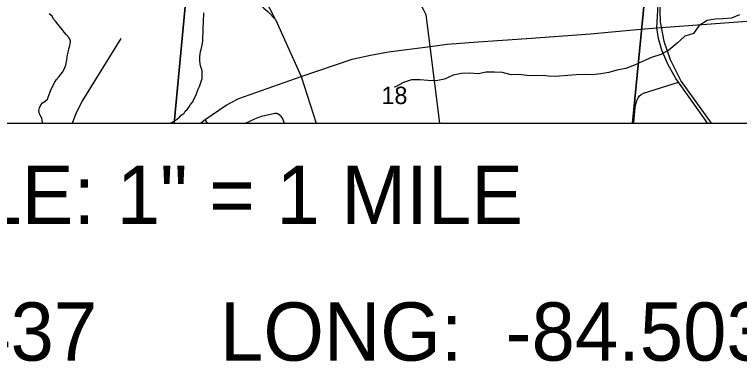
# Model space of a CAD drawing. Extents: x 0 to 34, y 0 to 22.
# Drawn here: x 12.335 to 14.078, y 12.863 to 13.697 of the extents above; entities that cross this region are included whole.
import ezdxf

# ---------------------------------------------------------------- set-up
doc = ezdxf.new("R2010")
doc.units = 0
for name, color, linetype in [('GM_X_City_Street', 7, 'Continuous'), ('GM_X_County_Road', 7, 'Continuous'), ('GM_X_Minor_River', 7, 'Continuous'), ('GM_X_Rail_Line', 7, 'Continuous'), ('GM_X_Section_Text', 7, 'Continuous'), ('GM_X_State_Route', 7, 'Continuous'), ('GM_X_Unincorporated', 7, 'Continuous'), ('SC_Scratch1', 7, 'Continuous'), ('SH_Border', 7, 'Continuous'), ('SH_Cut_Line', 7, 'Continuous'), ('SH_Text', 7, 'Continuous')]:
    doc.layers.add(name, color=color, linetype=linetype)

msp = doc.modelspace()

# ---------------------------------------------------------------- linework, layer by layer
at = {"layer": 'GM_X_City_Street'}
for p, q in [((13.8239, 13.4361), (13.8268, 13.4653)), ((12.7993, 13.4361), (12.7933, 13.4445))]:
    msp.add_line(p, q, dxfattribs=at)
for points in [[(12.9623, 13.6851), (12.8994, 13.8085), (12.8715, 13.8632), (12.8578, 13.8901), (12.8505, 13.9105), (12.8446, 13.9407), (12.8435, 13.9677), (12.8438, 13.9783), (12.8457, 13.9893), (12.8504, 14.009), (12.8817, 14.1527), (12.8925, 14.1925), (12.8989, 14.2158), (12.9063, 14.2462), (12.9222, 14.3585), (12.9265, 14.415), (12.9313, 14.4767), (12.9351, 14.5269), (12.9392, 14.5807), (12.95, 14.7552), (12.952, 14.774), (12.9626, 14.8755)], [(13.3578, 13.4361), (13.3342, 13.6203), (13.3325, 13.6336), (13.3249, 13.6963), (13.319, 13.7076), (13.2794, 13.7869), (13.263, 13.8203), (13.2618, 13.8264), (13.2608, 13.8314), (13.2578, 13.8677), (13.2541, 13.9068), (13.2453, 14.0017), (13.2455, 14.003), (13.2472, 14.0119), (13.2511, 14.0395), (13.2557, 14.0947), (13.2698, 14.1496)], [(12.4757, 13.8222), (12.6105, 13.8284), (12.617, 13.8278), (12.6302, 13.8255), (12.6712, 13.8157), (12.7281, 13.802), (12.7412, 13.7967), (12.7696, 13.7856), (12.8397, 13.7576), (12.923, 13.7221), (12.925, 13.7206), (12.9346, 13.7118), (12.9439, 13.7039), (12.9623, 13.6851), (13.0243, 13.5477), (13.0606, 13.4361)], [(12.4748, 13.4361), (12.4753, 13.4382), (12.484, 13.4615), (12.4973, 13.4877), (12.5915, 13.6389)], [(13.8378, 13.5016), (13.8416, 13.5046), (13.8472, 13.5076), (13.9316, 13.5344)], [(13.8268, 13.4653), (13.8281, 13.4792), (13.8316, 13.4904), (13.8341, 13.4963), (13.8378, 13.5016)], [(12.8914, 13.4361), (12.8917, 13.4363), (12.9129, 13.4463), (12.9286, 13.4527), (12.9611, 13.4597), (12.9645, 13.4597), (12.9667, 13.4592), (12.9683, 13.4588), (12.9692, 13.4583), (12.9713, 13.4565), (12.9741, 13.4539), (12.9779, 13.4489), (12.98, 13.4455), (12.9833, 13.4361)]]:
    msp.add_lwpolyline(points, dxfattribs=at)
at = {"layer": 'GM_X_County_Road'}
for points in [[(13.8794, 13.6645), (14.1179, 13.6823), (14.2361, 13.6935), (14.2709, 13.6989), (14.3163, 13.7106), (14.3538, 13.7272), (14.3972, 13.7554), (14.4369, 13.7864), (14.4688, 13.8215), (14.4974, 13.8598), (14.5112, 13.8856), (14.5228, 13.9135), (14.5528, 14.018)], [(12.7819, 13.4361), (12.7933, 13.4445), (12.844, 13.479), (12.8556, 13.4851), (12.8744, 13.4952), (13.0243, 13.5477), (13.1468, 13.5892), (13.1905, 13.5995), (13.2345, 13.6071), (13.3342, 13.6203), (13.3755, 13.6257), (13.4494, 13.6316), (13.5668, 13.6391), (13.7196, 13.6508), (13.831, 13.6611), (13.8319, 13.6612)], [(13.8319, 13.6612), (13.8397, 13.662), (13.8794, 13.6645)]]:
    msp.add_lwpolyline(points, dxfattribs=at)
at = {"layer": 'GM_X_Minor_River'}
for points in [[(12.402, 13.4361), (12.402, 13.4372), (12.401, 13.4433), (12.4007, 13.4478), (12.397, 13.4536), (12.3949, 13.4582), (12.3935, 13.4662), (12.3948, 13.4723), (12.3983, 13.4795), (12.4022, 13.4843), (12.4088, 13.4888), (12.4142, 13.4936), (12.4158, 13.4985), (12.4186, 13.5049), (12.4206, 13.511), (12.4226, 13.5159), (12.4254, 13.5219), (12.4281, 13.5275), (12.4321, 13.5347), (12.436, 13.5407), (12.4426, 13.5478), (12.4461, 13.5534), (12.4508, 13.5594), (12.456, 13.5696), (12.458, 13.5749), (12.4609, 13.5881), (12.4618, 13.5946), (12.4626, 13.6003), (12.4644, 13.6097), (12.4656, 13.6147), (12.4672, 13.6196), (12.4689, 13.6256), (12.4694, 13.6325), (12.4676, 13.6374), (12.4658, 13.642), (12.4591, 13.649), (12.4543, 13.6544), (12.4494, 13.6606), (12.4424, 13.6699), (12.438, 13.6749), (12.4339, 13.6803), (12.4283, 13.6861), (12.4251, 13.6931), (12.418, 13.6989)], [(12.7106, 13.4361), (12.711, 13.4363), (12.7171, 13.44), (12.7244, 13.4448), (12.7318, 13.45), (12.736, 13.4548), (12.7426, 13.46), (12.7453, 13.4645), (12.7504, 13.469), (12.7551, 13.4754), (12.7578, 13.481), (12.7633, 13.487), (12.7664, 13.4934), (12.7692, 13.4987), (12.7728, 13.5062), (12.7744, 13.5115), (12.7768, 13.5179), (12.7796, 13.5243), (12.7824, 13.5311), (12.7848, 13.5383), (12.7857, 13.5428), (12.786, 13.5592), (12.7853, 13.5649), (12.7832, 13.5714), (12.7814, 13.5787), (12.7805, 13.5867), (12.7807, 13.5958), (12.7812, 13.6015), (12.7824, 13.6083), (12.7837, 13.6128), (12.7849, 13.6197), (12.7866, 13.6284), (12.7875, 13.6333), (12.7877, 13.6443), (12.7882, 13.6519), (12.7884, 13.6569), (12.7889, 13.6641), (12.7895, 13.6785), (12.79, 13.701)], [(14.0781, 13.6965), (14.0592, 13.6878), (14.0387, 13.6863), (14.0197, 13.6859), (14.0003, 13.6829), (13.9806, 13.6699), (13.9673, 13.651), (13.9468, 13.6445), (13.9278, 13.6278), (13.9084, 13.6111), (13.8891, 13.6008), (13.8667, 13.594), (13.8465, 13.5845), (13.826, 13.5754), (13.8048, 13.5674), (13.7835, 13.5629), (13.7641, 13.5579), (13.7448, 13.5542), (13.7239, 13.5523), (13.7045, 13.553), (13.6856, 13.5523), (13.6654, 13.55), (13.6449, 13.5485), (13.6252, 13.5481), (13.6062, 13.55), (13.5872, 13.5492), (13.5667, 13.5507), (13.5477, 13.5526), (13.5288, 13.5519), (13.5086, 13.5572), (13.4893, 13.5587), (13.4691, 13.5583), (13.4494, 13.5545), (13.4293, 13.5557), (13.4095, 13.5553), (13.3898, 13.5515), (13.3689, 13.5413), (13.3484, 13.5375), (13.329, 13.5382), (13.3101, 13.5397), (13.2896, 13.5401), (13.2698, 13.5333), (13.2508, 13.523), (13.2481, 13.5223)]]:
    msp.add_lwpolyline(points, dxfattribs=at)
at = {"layer": 'GM_X_Rail_Line'}
msp.add_lwpolyline([(13.9251, 15.0074), (13.9437, 14.8982), (13.9491, 14.8375), (13.948, 14.7771), (13.9136, 14.3852), (13.8994, 14.3257), (13.8789, 14.2591), (13.872, 14.2266), (13.8727, 14.1891), (13.8776, 14.1566), (13.896, 14.1038), (13.9123, 14.0629), (13.914, 14.0319), (13.9078, 13.9882), (13.8857, 13.7329), (13.8873, 13.679), (13.8962, 13.6329), (13.9115, 13.589), (13.9381, 13.5363), (14.0101, 13.4361)], dxfattribs=at)
at = {"layer": 'GM_X_State_Route'}
msp.add_line((13.8794, 13.6645), (13.8809, 13.6931), dxfattribs=at)
for points in [[(13.8809, 13.6931), (13.8823, 13.7217), (13.8825, 13.7274), (13.8831, 13.7389), (13.885, 13.759)], [(13.9213, 13.5501), (13.9058, 13.5773), (13.8911, 13.6111), (13.883, 13.639), (13.8794, 13.6645)], [(14.0015, 13.4361), (13.9966, 13.443), (13.9316, 13.5344), (13.9251, 13.5435), (13.9213, 13.5501)]]:
    msp.add_lwpolyline(points, dxfattribs=at)
at = {"layer": 'GM_X_Unincorporated'}
for points in [[(11.7445, 13.4361), (12.7189, 13.4361), (12.7978, 14.2768), (11.8044, 14.1529)], [(12.7189, 13.4361), (13.821, 13.4361), (13.8744, 13.9883), (12.7978, 14.2768)], [(13.821, 13.4361), (14.8314, 13.4361), (14.8885, 14.0324), (13.8744, 13.9883)]]:
    msp.add_lwpolyline(points, close=True, dxfattribs=at)
at = {"layer": 'SC_Scratch1'}
msp.add_line((1.5, 13.4361), (32, 13.4361), dxfattribs=at)
msp.add_lwpolyline([(9.6328, 13.4361), (15.8393, 13.4361)], dxfattribs=at)
at = {"layer": 'SH_Border'}
msp.add_lwpolyline([(9.3, 20.2361), (9.3, 13.4361), (16.1, 13.4361), (16.1, 20.2361)], close=True, dxfattribs=at)
at = {"layer": 'SH_Cut_Line'}
msp.add_lwpolyline([(9.3, 13.4361), (16.1, 13.4361), (16.1, 14.8738), (15.9769, 14.894), (15.8407, 14.9188), (15.7547, 14.933), (15.5826, 14.9621), (15.5154, 14.9734), (15.3254, 15.0063), (15.1228, 15.0411), (14.9881, 15.0623), (14.5054, 15.0324), (14.0783, 15.001), (13.9652, 14.9956), (13.9262, 15.0068), (13.1413, 15.2326), (12.9952, 15.2762), (12.8889, 15.308), (11.871, 15.1527)], dxfattribs=at)

# ---------------------------------------------------------------- texts
at = {"layer": 'GM_X_Section_Text'}
msp.add_text('18', height=0.04186, rotation=0, dxfattribs=at).set_placement((13.2173, 13.4817))
at = {"layer": 'SH_Text'}
for s, p in [('SCALE: 1" = 1 MILE', (11.8627, 13.1936)), ('LAT:  39.329437', (11.1492, 12.8651)), ('LONG:  -84.503175', (12.8292, 12.8651))]:
    msp.add_text(s, height=0.14, dxfattribs=at).set_placement(p)

doc.saveas('drawing.dxf')
